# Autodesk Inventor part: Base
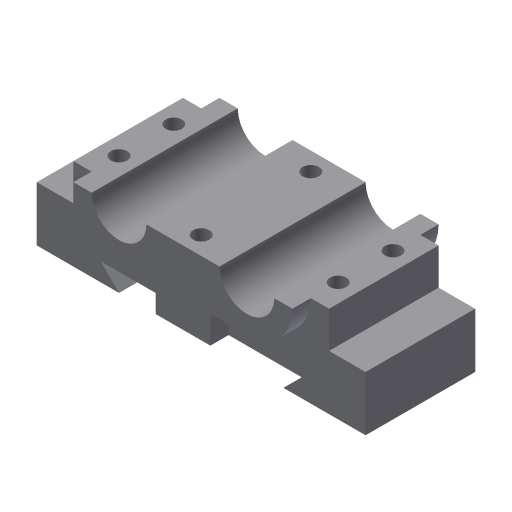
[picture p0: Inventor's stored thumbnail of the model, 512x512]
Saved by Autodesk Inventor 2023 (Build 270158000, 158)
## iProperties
Shininess: 77.0
Length Units: 11269
Angle Units: 11279
Time Units: 11290
Mass Units: 11283
Length Display Precision: 3
Angle Display Precision: 2
Created: 2002-02
Part Number: Base
Document SubType Name: Modeling
Designer: ***
Density: 1 g/cm^3
Material: Generic
Appearance: Default
Density: 0.0
Volumn: 0.0
Area: 0.0
PropertySet Name: Model Information
Control State: 0
Master: False
Checked Out: False
Author: ***
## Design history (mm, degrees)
sketch "Sketch2"
  geometry: L1 (-10.066, -1.263)-(24.934, -1.263); L2 (37.434, 11.237)-(32.434, 11.237); L3 (17.434, 11.237)-(-2.566, 11.237); L4 (-17.566, 11.237)-(-22.566, 11.237); A1 r 12.5 centre (-10.066, 11.237) between (-22.566, 11.237) and (-10.066, -1.263); A2 r 12.5 centre (24.934, 11.237) between (24.934, -1.263) and (37.434, 11.237); A3 r 7.5 centre (24.934, 11.237) between (17.434, 11.237) and (32.434, 11.237); A4 r 7.5 centre (-10.066, 11.237) between (-17.566, 11.237) and (-2.566, 11.237)
  constraints: 8 end point, 8 point on circle, 4 centre point, 3 horizontal, 3 parallel, 2 coincident, 2 equal radius, 2 tangent
  dimensions: "d0" = 12.5 radius of A1; "d1" = 7.5 radius of A4; "d2" = 35 distance of A1.centre A2.centre; "d3" = 12.5 distance between parallel lines of L3 L1
extrude "Extrusion1" new body sketch "Sketch2" stored distance "d4" = 40; taper "d5" = 0 deg
sketch "Sketch4"
  geometry: L1 (-27.566, 1.237)-(-37.566, 1.237); L2 (-37.566, 1.237)-(-37.566, -13.763); L3 (-37.566, -13.763)-(-15.066, -13.763); L4 (-15.066, -13.763)-(-20.066, -8.763); L5 (-20.066, -8.763)-(34.934, -8.763); L6 (34.934, -8.763)-(29.934, -13.763); L7 (29.934, -13.763)-(52.434, -13.763); L8 (52.434, -13.763)-(52.434, 1.237); L9 (52.434, 1.237)-(42.434, 1.237); L10 (24.934, -1.263)-(-10.066, -1.263); L11 (-17.566, 11.237)-(-22.566, 11.237) reference; L12 (37.434, 11.237)-(32.434, 11.237) reference; L13 (-22.566, 11.237)-(-27.566, 11.237); L14 (-27.566, 11.237)-(-27.566, 1.237); L15 (37.434, 11.237)-(42.434, 11.237); L16 (42.434, 11.237)-(42.434, 1.237); A1 r 12.5 centre (24.934, 11.237) between (24.934, -1.263) and (37.434, 11.237); A2 r 12.5 centre (-10.066, 11.237) between (-22.566, 11.237) and (-10.066, -1.263); A3 r 12.5 centre (24.934, 11.237) between (24.934, -1.263) and (37.434, 11.237) reference; A4 r 12.5 centre (-10.066, 11.237) between (-22.566, 11.237) and (-10.066, -1.263) reference
  constraints: 28 end point, 6 perpendicular, 5 equal length, 4 concentric, 4 parallel, 4 point on circle, 2 centre point, 2 collinear, 1 tangent
  dimensions: "d12" = 15 distance of L1.end L2.end; "d13" = 25 distance from line of L3 L11.end; "d14" = 90 distance between parallel lines of L2 L8; "d15" = 5 distance between parallel lines of L5 L7; "d16" = 22.5 distance of L2.end L3.end; "d24" = 5 distance of L12.start L15.end; "d25" = 15 distance from line of L8 L12.start
extrude "Extrusion3" join sketch "Sketch4" stored distance "d17" = 30; taper "d18" = 0 deg
sketch "Sketch5"
  geometry: L1 (-14.934, -1.263)-(0.066, -1.263); L2 (0.066, -1.263)-(0.066, -8.763); L3 (0.066, -8.763)-(-14.934, -8.763); L4 (-14.934, -8.763)-(-14.934, -1.263); L5 (10.066, -1.263)-(-24.934, -1.263) reference; 1 further point
  constraints: 8 end point, 2 parallel, 1 collinear, 1 horizontal, 1 perpendicular
  dimensions: "d19" = 7.5 distance of L1.end L2.end; "d20" = 15 distance of L2.end L3.end; "d21" = 15 distance from line of point (-29.934, -13.763) L4
extrude "Extrusion4" join sketch "Sketch5" distance "d22" = 40; taper "d23" = 0 deg
sketch "Sketch6"
  geometry: L1 (-5, -35)-(0, -35) reference; L2 (-5, -35)-(-5, -5) reference; 1 further point
  dimensions: "d26" = 7.5 distance from line of L1 point (0, -27.5); "d27" = 5 distance from line of L2 point (0, -27.5)
hole "Hole1" sketch "Sketch6" at (0, -27.5) diameter "d28" = 4.5; stored, may be unused: countersink angle "d32" = 82 deg, drill point angle "d34" = 0 deg; dims "d29" = 6, "d30" = 4, "d31" = 2, "d33" = 15
pattern_linear "Rectangular Pattern1" dims "d37" = 60, "d40" = 15
sketch "Sketch7"
  geometry: L1 (-20, -40)-(-20, -35) reference; L2 (0, -40)-(20, -40) reference; 1 further point
  dimensions: "d41" = 30 distance from line of L1 point (10, -35); "d42" = 5 distance from line of L2 point (10, -35)
hole "Hole2" sketch "Sketch7" at (10, -35) diameter "d43" = 4.5; stored, may be unused: countersink angle "d47" = 82 deg, drill point angle "d49" = 0 deg; dims "d44" = 6, "d45" = 4, "d46" = 2, "d48" = 15
pattern_linear "Rectangular Pattern2" dims "d52" = 30
body "Solid1"
